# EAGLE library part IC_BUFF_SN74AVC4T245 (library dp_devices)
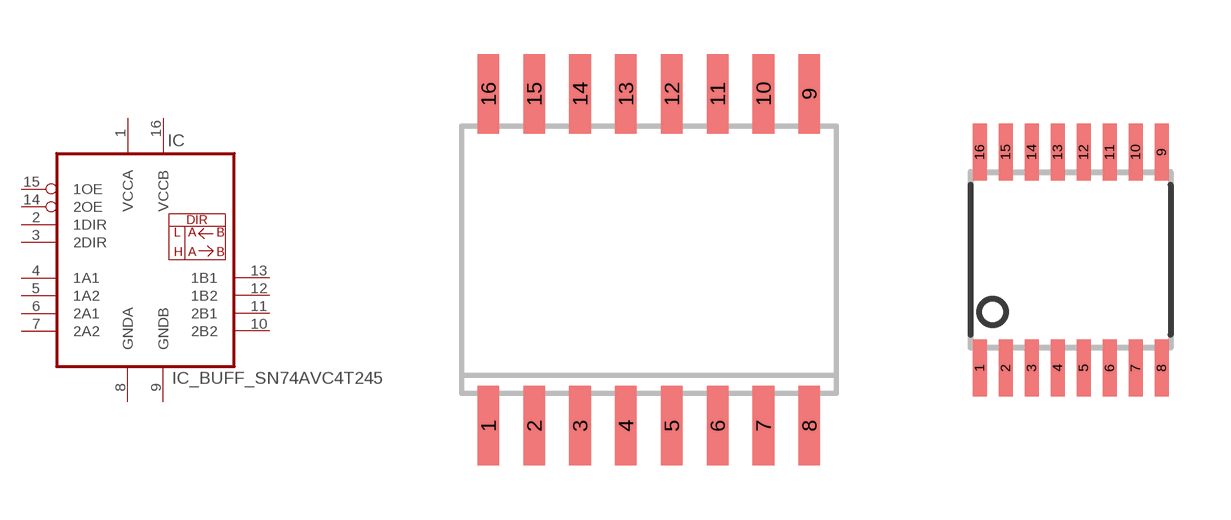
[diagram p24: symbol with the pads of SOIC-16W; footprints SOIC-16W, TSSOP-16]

Designator prefix IC

## IC_BUFF_SN74AVC4T245  [SOIC-16W]
1  VCCA  pwr
2  1DIR
3  2DIR
4  1A1
5  1A2
6  2A1
7  2A2
8  GNDA  pwr
9  GNDB  pwr
10  2B2
11  2B1
12  1B2
13  1B1
14  2OE
15  1OE
16  VCCB  pwr

## IC_BUFF_SN74AVC4T245PW  [TSSOP-16]
Pads as for SOIC-16W

## Footprint SOIC-16W (pad centres in mm)
smd 0.6 x 2.2: 1 -4.445,-4.6; 2 -3.175,-4.6; 3 -1.905,-4.6; 4 -0.635,-4.6; 5 0.635,-4.6; 6 1.905,-4.6; 7 3.175,-4.6; 8 4.445,-4.6; 9 4.445,4.6; 10 3.175,4.6; 11 1.905,4.6; 12 0.635,4.6; 13 -0.635,4.6; 14 -1.905,4.6; 15 -3.175,4.6; 16 -4.445,4.6

## Footprint TSSOP-16 (pad centres in mm)
smd 0.35 x 1.43: 1 -2.275,-2.7; 2 -1.625,-2.7; 3 -0.975,-2.7; 4 -0.325,-2.7; 5 0.325,-2.7; 6 0.975,-2.7; 7 1.625,-2.7; 8 2.275,-2.7; 9 2.275,2.7; 10 1.625,2.7; 11 0.975,2.7; 12 0.325,2.7; 13 -0.325,2.7; 14 -0.975,2.7; 15 -1.625,2.7; 16 -2.275,2.7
